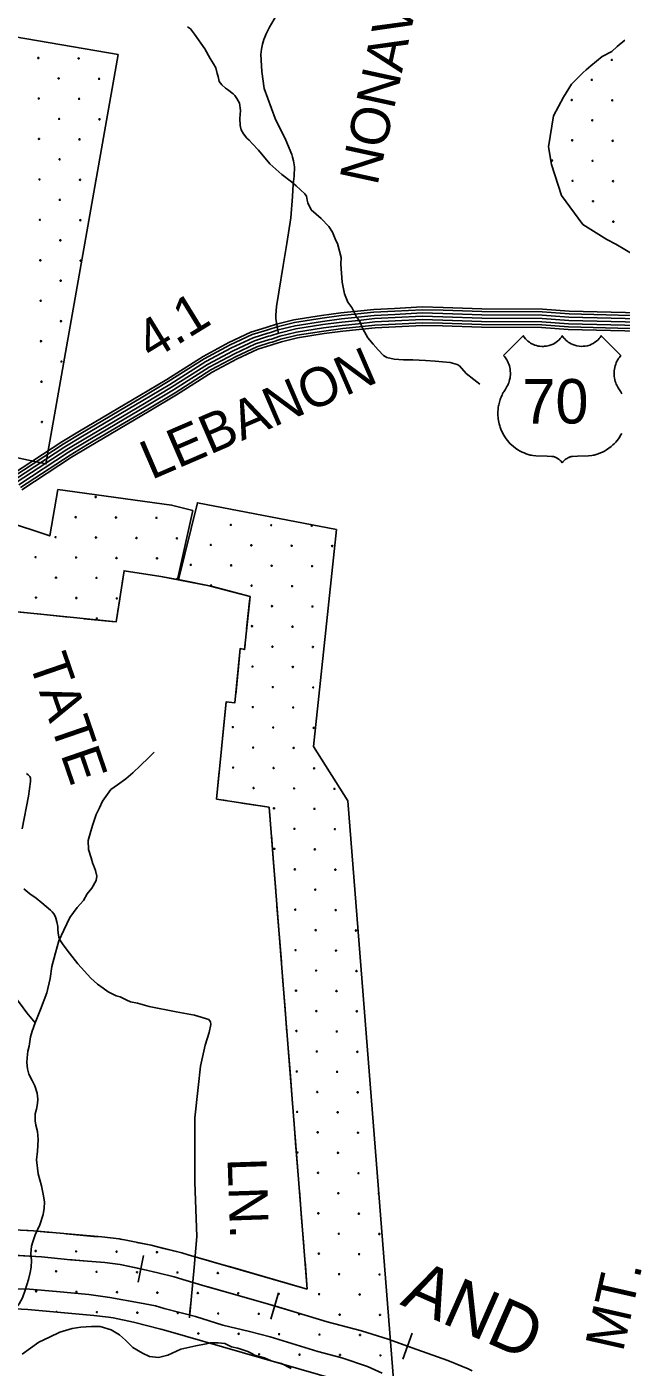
# Model space of a CAD drawing. Extents: x 1788175 to 1969470, y 584502 to 738744.
# Drawn here: x 1809595 to 1815246, y 681239 to 693983 of the extents above; entities that cross this region are included whole.
import ezdxf

# ---------------------------------------------------------------- set-up
doc = ezdxf.new("R2010")
doc.units = 0
for name, color, linetype in [('DESIGN - CONTOURS - Intermediate with optional Text', 7, 'Continuous'), ('DESIGN - EROSION CONTROL - Devices', 7, 'Continuous'), ('DESIGN - ROW - Right-of-Way and Easement Labels', 7, 'Continuous'), ('DESIGN - SCRATCH - User 1', 7, 'Continuous'), ('DESIGN - TRAFFIC CONTROL PERMANENT - Signalization', 7, 'Continuous'), ('DESIGN - TRANSPORTATION - Text', 7, 'Continuous'), ('DESIGN - VEGETATION - Features with Text', 7, 'Continuous'), ('SURVEY - CENTERLINE - Preliminary Text', 7, 'Continuous'), ('SURVEY - CONTOURS - Index with Text', 7, 'Continuous'), ('SURVEY - DRAINAGE - Bridge Deck with Text', 7, 'Continuous'), ('SURVEY - TRANSPORTATION - Roads', 7, 'Continuous'), ('SURVEY - UTILITIES - Cable (Underground) with Text', 7, 'Continuous'), ('SURVEY - VEGETATION - Features with Text', 7, 'Continuous')]:
    doc.layers.add(name, color=color, linetype=linetype)

msp = doc.modelspace()

# ---------------------------------------------------------------- linework, layer by layer
at = {"layer": 'DESIGN - CONTOURS - Intermediate with optional Text'}
for p, q in [((1810652, 682047), (1810705, 682301)), ((1811914, 681697), (1811988, 681947)), ((1813170, 681317), (1813258, 681562))]:
    msp.add_line(p, q, dxfattribs=at)
for points in [[(1808939, 682334), (1809735, 682289), (1810009, 682261), (1810173, 682247), (1810338, 682233), (1810482, 682215), (1810703, 682169), (1810841, 682135), (1810997, 682097), (1811109, 682063), (1811292, 682010), (1811550, 681937), (1811894, 681839), (1812169, 681757), (1812452, 681672), (1812778, 681584), (1813029, 681506), (1813304, 681407), (1813599, 681303), (1813791, 681223)], [(1809367, 682310), (1809735, 682289), (1810009, 682261), (1810025, 682259)], [(1810025, 682259), (1810173, 682247), (1810338, 682233), (1810482, 682215), (1810679, 682174)], [(1810679, 682174), (1810703, 682169), (1810841, 682135), (1810997, 682097), (1811109, 682063), (1811292, 682010), (1811316, 682004)], [(1811316, 682004), (1811550, 681937), (1811894, 681839), (1811951, 681822)], [(1811951, 681822), (1812169, 681757), (1812452, 681672), (1812584, 681636)], [(1812584, 681636), (1812778, 681584), (1813029, 681506), (1813214, 681440)], [(1813214, 681440), (1813304, 681407), (1813599, 681303), (1813791, 681223), (1813830, 681206)]]:
    msp.add_lwpolyline(points, dxfattribs=at)
at = {"layer": 'DESIGN - EROSION CONTROL - Devices'}
for centre in [(1809704, 693686), (1810088, 693682), (1815157, 693668), (1809898, 693492), (1810283, 693488), (1814967, 693478), (1809708, 693301), (1810092, 693298), (1814776, 693287), (1815161, 693284), (1809902, 693107), (1810286, 693103), (1814971, 693093), (1809711, 692917), (1810096, 692913), (1814780, 692903), (1815165, 692899), (1809906, 692723), (1814590, 692712), (1814974, 692709), (1809715, 692532), (1810100, 692528), (1814784, 692518), (1815168, 692515), (1809909, 692338), (1814978, 692324), (1809719, 692148), (1810103, 692144), (1815172, 692130), (1809913, 691953), (1809723, 691763), (1810107, 691759), (1809917, 691569), (1809726, 691378), (1809920, 691184), (1809730, 690994), (1809924, 690800), (1809734, 690609), (1809738, 690225), (1809741, 689840), (1810249, 689512), (1810059, 689321), (1810443, 689318), (1810828, 689314), (1811534, 689247), (1811919, 689244), (1812304, 689240), (1809868, 689131), (1810253, 689127), (1810637, 689123), (1811022, 689120), (1811344, 689057), (1811729, 689053), (1812113, 689049), (1812498, 689046), (1809678, 688940), (1810063, 688937), (1810447, 688933), (1810832, 688929), (1811154, 688867), (1811538, 688863), (1811923, 688859), (1812307, 688855), (1809872, 688746), (1810257, 688743), (1811348, 688672), (1811732, 688669), (1812117, 688665), (1809682, 688556), (1810066, 688552), (1810451, 688548), (1811926, 688475), (1812311, 688471), (1810260, 688358), (1811736, 688284), (1812121, 688280), (1811930, 688090), (1812315, 688086), (1811740, 687900), (1812124, 687896), (1811934, 687705), (1812318, 687702), (1811744, 687515), (1812128, 687511), (1811553, 687325), (1811938, 687321), (1812322, 687317), (1811747, 687130), (1812132, 687127), (1811557, 686940), (1811941, 686936), (1812326, 686933), (1811751, 686746), (1812136, 686742), (1812520, 686738), (1811945, 686552), (1812330, 686548), (1812139, 686358), (1812524, 686354), (1811949, 686167), (1812333, 686163), (1812143, 685973), (1812528, 685969), (1812337, 685779), (1812147, 685589), (1812531, 685585), (1812341, 685394), (1812725, 685391), (1812150, 685204), (1812535, 685200), (1812345, 685010), (1812729, 685006), (1812154, 684819), (1812539, 684816), (1812348, 684625), (1812733, 684622), (1812158, 684435), (1812542, 684431), (1812352, 684241), (1812737, 684237), (1812162, 684050), (1812546, 684047), (1812356, 683856), (1812740, 683852), (1812165, 683666), (1812550, 683662), (1812360, 683472), (1812744, 683468), (1812169, 683281), (1812554, 683277), (1812363, 683087), (1812748, 683083), (1812557, 682893), (1812367, 682702), (1812752, 682699), (1812561, 682508), (1812946, 682505), (1809679, 682344), (1810063, 682340), (1810448, 682337), (1810833, 682333), (1812371, 682318), (1812755, 682314), (1809873, 682150), (1810258, 682146), (1810642, 682142), (1811027, 682139), (1811411, 682135), (1812565, 682124), (1812949, 682120), (1809683, 681960), (1810067, 681956), (1810452, 681952), (1810836, 681948), (1811221, 681945), (1811605, 681941), (1811990, 681937), (1812374, 681933), (1812759, 681930), (1810261, 681762), (1810646, 681758), (1811030, 681754), (1811415, 681750), (1811800, 681747), (1812184, 681743), (1812569, 681739), (1812953, 681736), (1811225, 681560), (1811609, 681556), (1811994, 681553), (1812378, 681549), (1812763, 681545), (1811803, 681362), (1812188, 681358), (1812572, 681355), (1812957, 681351)]:
    msp.add_circle(centre, 5.28, dxfattribs=at)
for centre, start, end in [((1810290, 692719), 130.2848, 209.7236), ((1811026, 688735), 44.9488, 290.1383), ((1812942, 682889), 98.5783, 270.4574), ((1809877, 681765), 321.2621, 208.4208)]:
    msp.add_arc(centre, 5.28, start, end, dxfattribs=at)
at = {"layer": 'DESIGN - SCRATCH - User 1'}
for p, q in [((1811049, 688726), (1811349, 688664)), ((1811349, 688664), (1811718, 688566)), ((1811399, 686640), (1811899, 686562)), ((1813094, 680961), (1812647, 686623)), ((1811899, 686562), (1812261, 681980))]:
    msp.add_line(p, q, dxfattribs=at)
for points in [[(1809243, 694669), (1809149, 693943), (1810462, 693718)], [(1815280, 693856), (1815207, 693796), (1815158, 693747), (1815064, 693699), (1814959, 693613), (1814913, 693573), (1814884, 693547), (1814774, 693438), (1814699, 693314), (1814602, 693135), (1814555, 692841), (1814582, 692673)], [(1810462, 693718), (1809776, 689827), (1809250, 689939), (1809219, 689666), (1809187, 689328), (1808480, 689389)], [(1814582, 692673), (1814680, 692378), (1814882, 692102), (1815111, 691962), (1815196, 691917), (1815368, 691816), (1815509, 691755), (1815664, 691688), (1815749, 691647), (1815916, 691574), (1816044, 691537), (1816113, 691512), (1816236, 691479), (1816378, 691451), (1816561, 691442), (1816683, 691464)], [(1811027, 688727), (1811172, 689383), (1810971, 689436), (1809890, 689583), (1809812, 689142), (1809382, 689286), (1809360, 689294)], [(1812539, 689204), (1811216, 689457), (1811036, 688726), (1811049, 688726)], [(1812647, 686623), (1812321, 687139), (1812539, 689204)], [(1809112, 688470), (1809253, 688445), (1810444, 688325), (1810520, 688811), (1810870, 688756), (1811027, 688727)], [(1811718, 688566), (1811665, 688062), (1811623, 688072), (1811574, 687557), (1811490, 687564), (1811399, 686640)], [(1812261, 681980), (1811129, 682307), (1811069, 682326), (1810777, 682398), (1810554, 682445), (1810473, 682458), (1810307, 682477), (1809659, 682535), (1808968, 682572), (1808879, 682574)], [(1808321, 681810), (1808942, 681823), (1809605, 681787), (1810231, 681730), (1810371, 681715), (1810417, 681707), (1810609, 681667), (1810870, 681602), (1810917, 681588), (1813094, 680961)]]:
    msp.add_lwpolyline(points, dxfattribs=at)
at = {"layer": 'DESIGN - TRANSPORTATION - Text'}
for points in [[(1811124, 693984), (1811150, 693964), (1811188, 693914), (1811288, 693772), (1811337, 693682), (1811369, 693632), (1811393, 693592), (1811405, 693538), (1811413, 693510), (1811425, 693464), (1811449, 693430), (1811483, 693400), (1811503, 693386), (1811557, 693346), (1811573, 693330), (1811593, 693302), (1811617, 693258), (1811627, 693186), (1811620, 693110), (1811622, 693044), (1811632, 693002), (1811654, 692966), (1811688, 692924), (1811708, 692904), (1811738, 692874), (1811798, 692810), (1811904, 692680), (1812019, 692580), (1812111, 692510), (1812157, 692472), (1812237, 692396), (1812253, 692372), (1812261, 692336), (1812267, 692310), (1812297, 692244), (1812395, 692160), (1812466, 692084), (1812500, 692030), (1812532, 691952), (1812548, 691921)], [(1812548, 691921), (1812585, 691789), (1812581, 691725), (1812592, 691555), (1812616, 691445), (1812648, 691364), (1812684, 691314), (1812730, 691226), (1812762, 691180), (1812787, 691119), (1812804, 691084), (1812836, 691027), (1812889, 690967), (1812935, 690910), (1812985, 690857), (1813017, 690839), (1813088, 690822), (1813176, 690815), (1813265, 690815), (1813385, 690811), (1813478, 690804), (1813548, 690797), (1813619, 690790), (1813687, 690772), (1813708, 690758), (1813772, 690687), (1813846, 690630), (1813901, 690584)], [(1810807, 687087), (1810751, 687031), (1810675, 686959), (1810603, 686889), (1810535, 686833), (1810457, 686776), (1810395, 686730), (1810314, 686620), (1810286, 686558), (1810254, 686494), (1810218, 686390), (1810196, 686314), (1810178, 686248), (1810180, 686160), (1810206, 686082), (1810222, 686025), (1810228, 686013), (1810247, 685961), (1810259, 685909), (1810255, 685867), (1810213, 685793), (1810169, 685741), (1810133, 685675), (1810073, 685609), (1810003, 685513), (1809947, 685395), (1809899, 685294), (1809868, 685178), (1809834, 685050), (1809816, 684936), (1809786, 684798), (1809726, 684640), (1809674, 684514)], [(1808495, 686196), (1808563, 686142), (1808618, 686060), (1808618, 685952), (1808604, 685843), (1808604, 685762), (1808618, 685694), (1808631, 685585), (1808699, 685477), (1808767, 685409), (1808835, 685314), (1808916, 685192), (1808970, 685111), (1809011, 685084), (1809065, 685056), (1809147, 685016), (1809241, 684948), (1809323, 684894), (1809377, 684866), (1809431, 684826), (1809526, 684704), (1809594, 684609), (1809674, 684514)], [(1809674, 684514), (1809647, 684433), (1809630, 684380), (1809616, 684290), (1809603, 684244), (1809597, 684181), (1809596, 684137), (1809601, 684075), (1809614, 684024), (1809646, 683966), (1809670, 683914), (1809694, 683845), (1809700, 683787), (1809697, 683745), (1809686, 683692), (1809675, 683648), (1809674, 683581), (1809680, 683540), (1809696, 683481), (1809704, 683405), (1809695, 683292), (1809688, 683212), (1809703, 683077), (1809735, 682963), (1809754, 682868), (1809762, 682808), (1809761, 682752), (1809750, 682690)], [(1809750, 682690), (1809719, 682594), (1809675, 682496), (1809652, 682431), (1809638, 682389), (1809633, 682319), (1809640, 682253), (1809636, 682189), (1809627, 682140), (1809611, 682072), (1809580, 681970), (1809555, 681899), (1809522, 681840), (1809488, 681796), (1809455, 681755), (1809437, 681706), (1809422, 681645), (1809417, 681585), (1809398, 681518), (1809385, 681432), (1809366, 681379), (1809350, 681338), (1809333, 681296), (1809312, 681251)], [(1809552, 681364), (1809710, 681478), (1809810, 681525), (1809910, 681571), (1810025, 681607), (1810108, 681619), (1810210, 681625), (1810292, 681627), (1810398, 681593), (1810476, 681547), (1810532, 681497), (1810604, 681427), (1810694, 681372), (1810760, 681342), (1810846, 681332), (1810936, 681352), (1811060, 681412), (1811202, 681441), (1811300, 681460), (1811337, 681471), (1811413, 681471), (1811477, 681464), (1811541, 681434), (1811601, 681419), (1811695, 681389), (1811733, 681370)], [(1811733, 681370), (1811759, 681355), (1811855, 681327), (1811917, 681299), (1812017, 681273), (1812107, 681227)]]:
    msp.add_lwpolyline(points, dxfattribs=at)
at = {"layer": 'SURVEY - CENTERLINE - Preliminary Text'}
for points in [[(1815687, 691256), (1814752, 691279), (1814497, 691297), (1813922, 691301), (1813553, 691314), (1813353, 691319), (1813092, 691305), (1812893, 691296), (1812738, 691278), (1812580, 691262), (1812398, 691238), (1812135, 691196), (1811968, 691155), (1811888, 691129), (1811870, 691125), (1811726, 691080), (1811517, 690981), (1811270, 690849), (1810925, 690631), (1810669, 690477), (1810095, 690139), (1809927, 690038), (1809457, 689730)], [(1815687, 691230), (1814751, 691253), (1814496, 691272), (1813921, 691275), (1813552, 691288), (1813353, 691293), (1813093, 691280), (1812895, 691270), (1812741, 691253), (1812583, 691237), (1812402, 691213), (1812140, 691171), (1811975, 691131), (1811895, 691104), (1811877, 691100), (1811736, 691056), (1811528, 690958), (1811282, 690827), (1810939, 690609), (1810682, 690455), (1810108, 690117), (1809941, 690016), (1809470, 689708)], [(1815686, 691199), (1814749, 691222), (1814495, 691241), (1813921, 691244), (1813551, 691257), (1813354, 691262), (1813095, 691249), (1812898, 691239), (1812744, 691222), (1812587, 691206), (1812406, 691182), (1812146, 691141), (1811984, 691101), (1811903, 691074), (1811885, 691070), (1811747, 691027), (1811542, 690930), (1811298, 690800), (1810955, 690583), (1810698, 690429), (1810124, 690090), (1809957, 689990), (1809487, 689682)], [(1815685, 691168), (1814748, 691191), (1814494, 691210), (1813920, 691213), (1813550, 691226), (1813354, 691231), (1813096, 691218), (1812900, 691208), (1812747, 691191), (1812590, 691175), (1812410, 691152), (1812152, 691110), (1811992, 691071), (1811912, 691044), (1811893, 691040), (1811758, 690998), (1811556, 690902), (1811314, 690773), (1810971, 690557), (1810714, 690402), (1810140, 690063), (1809974, 689964), (1809503, 689656)], [(1815684, 691137), (1814746, 691160), (1814493, 691179), (1813919, 691182), (1813549, 691195), (1813355, 691200), (1813098, 691187), (1812903, 691177), (1812750, 691160), (1812594, 691144), (1812415, 691121), (1812159, 691080), (1812001, 691041), (1811920, 691014), (1811901, 691010), (1811770, 690969), (1811570, 690875), (1811329, 690746), (1810988, 690530), (1810730, 690375), (1810156, 690037), (1809990, 689938), (1809519, 689629)], [(1815684, 691106), (1814745, 691129), (1814491, 691148), (1813919, 691151), (1813548, 691164), (1813355, 691169), (1813099, 691156), (1812905, 691146), (1812754, 691129), (1812598, 691114), (1812419, 691090), (1812165, 691050), (1812009, 691012), (1811928, 690984), (1811909, 690980), (1811781, 690940), (1811584, 690847), (1811345, 690720), (1811004, 690504), (1810746, 690349), (1810171, 690010), (1810007, 689911), (1809535, 689603)], [(1815683, 691082), (1814743, 691104), (1814490, 691123), (1813918, 691127), (1813548, 691140), (1813356, 691144), (1813101, 691131), (1812907, 691122), (1812756, 691105), (1812600, 691089), (1812423, 691066), (1812170, 691025), (1812016, 690988), (1811935, 690961), (1811915, 690956), (1811790, 690917), (1811595, 690825), (1811357, 690698), (1811017, 690483), (1810758, 690327), (1810184, 689989), (1810020, 689890), (1809548, 689582)]]:
    msp.add_lwpolyline(points, dxfattribs=at)
at = {"layer": 'SURVEY - CONTOURS - Index with Text'}
for points in [[(1812014, 694169), (1811901, 693978), (1811875, 693923), (1811847, 693861), (1811835, 693819), (1811825, 693771), (1811820, 693718), (1811829, 693559), (1811852, 693397), (1811956, 693110), (1812057, 692904), (1812113, 692768), (1812121, 692744), (1812129, 692708), (1812139, 692650), (1812136, 692562), (1812128, 692488), (1812122, 692370), (1812104, 692166), (1812067, 691923), (1812032, 691714), (1811990, 691461), (1811970, 691322), (1811962, 691242), (1811962, 691207), (1811988, 691063)], [(1812974, 681183), (1812833, 681247), (1812591, 681329), (1812361, 681387), (1812113, 681466), (1811908, 681528), (1811712, 681580), (1811458, 681638), (1811198, 681722), (1810902, 681797), (1810817, 681821), (1810667, 681851), (1810385, 681901), (1810183, 681930), (1809877, 681958), (1809619, 681980), (1809379, 681987)]]:
    msp.add_lwpolyline(points, dxfattribs=at)
at = {"layer": 'SURVEY - DRAINAGE - Bridge Deck with Text'}
for points in [[(1814127, 690858), (1814315, 691045), (1814325, 691031), (1814337, 691016), (1814349, 691004), (1814360, 690994), (1814373, 690985), (1814385, 690976), (1814398, 690969), (1814412, 690962), (1814425, 690957), (1814442, 690952), (1814457, 690948), (1814474, 690946), (1814492, 690944), (1814500, 690944), (1814508, 690944), (1814516, 690945), (1814526, 690946), (1814536, 690947), (1814550, 690950), (1814562, 690953), (1814580, 690959), (1814598, 690967), (1814614, 690975), (1814628, 690985), (1814642, 690995), (1814655, 691007), (1814667, 691020), (1814678, 691033), (1814686, 691045), (1814693, 691035), (1814702, 691024), (1814710, 691015), (1814719, 691005), (1814731, 690995), (1814743, 690985), (1814756, 690977), (1814770, 690969), (1814786, 690961), (1814804, 690955), (1814826, 690949), (1814847, 690946), (1814865, 690944), (1814884, 690945), (1814905, 690947), (1814925, 690951), (1814947, 690957), (1814965, 690965), (1814980, 690972), (1814996, 690983), (1815011, 690993), (1815027, 691007), (1815037, 691019), (1815047, 691030), (1815057, 691045), (1815244, 690858)], [(1814127, 690858), (1814137, 690848), (1814145, 690837), (1814152, 690826), (1814159, 690816), (1814166, 690803), (1814172, 690789), (1814178, 690775), (1814183, 690760), (1814187, 690745), (1814190, 690729), (1814192, 690712), (1814193, 690690), (1814193, 690673), (1814191, 690658), (1814189, 690644), (1814185, 690625), (1814181, 690611), (1814177, 690598), (1814172, 690586), (1814167, 690576), (1814159, 690562), (1814152, 690550), (1814142, 690532), (1814129, 690511), (1814125, 690505), (1814119, 690494), (1814113, 690481), (1814109, 690472), (1814104, 690460), (1814100, 690450), (1814096, 690439), (1814092, 690427), (1814088, 690415), (1814085, 690401), (1814082, 690390), (1814080, 690378), (1814078, 690366), (1814076, 690353), (1814075, 690342), (1814074, 690330), (1814074, 690319), (1814074, 690308), (1814074, 690296), (1814074, 690284), (1814075, 690270), (1814077, 690254), (1814079, 690239), (1814082, 690224), (1814085, 690208), (1814091, 690189), (1814095, 690175), (1814102, 690157), (1814108, 690143), (1814113, 690132), (1814120, 690117), (1814130, 690100), (1814139, 690085), (1814151, 690067), (1814164, 690051), (1814177, 690035), (1814192, 690019), (1814204, 690007), (1814221, 689993), (1814241, 689977), (1814265, 689961), (1814285, 689949), (1814305, 689939), (1814323, 689931), (1814344, 689923), (1814363, 689917), (1814382, 689911), (1814392, 689909), (1814405, 689908), (1814435, 689905), (1814541, 689902), (1814588, 689899), (1814593, 689899), (1814598, 689897), (1814603, 689896), (1814608, 689895), (1814613, 689893), (1814617, 689891), (1814622, 689889), (1814627, 689887), (1814632, 689885), (1814636, 689883), (1814640, 689880), (1814648, 689875), (1814658, 689868), (1814666, 689861), (1814674, 689853), (1814680, 689846), (1814686, 689838)], [(1815244, 690858), (1815235, 690848), (1815227, 690837), (1815219, 690826), (1815213, 690816), (1815206, 690803), (1815199, 690789), (1815194, 690775), (1815189, 690760), (1815185, 690745), (1815182, 690729), (1815179, 690712), (1815178, 690690), (1815179, 690673), (1815180, 690658), (1815182, 690644), (1815186, 690625), (1815190, 690611), (1815194, 690598), (1815199, 690586), (1815204, 690576), (1815212, 690562), (1815219, 690550), (1815230, 690532), (1815243, 690511), (1815246, 690505), (1815252, 690494)], [(1815251, 690117), (1815241, 690100), (1815232, 690085), (1815220, 690067), (1815208, 690051), (1815194, 690035), (1815180, 690019), (1815167, 690007), (1815150, 689993), (1815130, 689977), (1815106, 689961), (1815086, 689949), (1815067, 689939), (1815048, 689931), (1815028, 689923), (1815008, 689917), (1814989, 689911), (1814979, 689909), (1814967, 689908), (1814936, 689905), (1814831, 689902), (1814783, 689899), (1814779, 689899), (1814774, 689897), (1814769, 689896), (1814764, 689895), (1814759, 689893), (1814754, 689891), (1814749, 689889), (1814745, 689887), (1814739, 689885), (1814736, 689883), (1814732, 689880), (1814723, 689875), (1814714, 689868), (1814705, 689861), (1814698, 689853), (1814691, 689846), (1814686, 689838)]]:
    msp.add_lwpolyline(points, dxfattribs=at)
at = {"layer": 'SURVEY - TRANSPORTATION - Roads'}
for points in [[(1809552, 686356), (1809610, 686668), (1809630, 686806), (1809631, 686822), (1809630, 686830), (1809629, 686840), (1809625, 686850), (1809622, 686856), (1809613, 686866), (1809609, 686870), (1809593, 686884)], [(1810647, 684699), (1810581, 684713), (1810545, 684729), (1810483, 684759), (1810443, 684771), (1810367, 684809), (1810321, 684843), (1810267, 684881), (1810203, 684937), (1810081, 685073), (1810002, 685177), (1809940, 685255), (1809910, 685301), (1809900, 685327), (1809893, 685370), (1809891, 685398), (1809888, 685429), (1809881, 685473), (1809871, 685508), (1809864, 685526), (1809850, 685548), (1809837, 685569), (1809819, 685585), (1809739, 685653), (1809683, 685699), (1809623, 685741), (1809567, 685787)], [(1811143, 681710), (1811186, 682188), (1811210, 682482), (1811193, 682998), (1811192, 683611), (1811223, 683899), (1811245, 684102), (1811292, 684302), (1811330, 684422), (1811344, 684496), (1811340, 684524), (1811324, 684544), (1811302, 684552), (1811254, 684568), (1811188, 684586), (1811014, 684618), (1810759, 684668), (1810647, 684699)]]:
    msp.add_lwpolyline(points, dxfattribs=at)
at = {"layer": 'SURVEY - UTILITIES - Cable (Underground) with Text'}
msp.add_lwpolyline([(1811153, 681852), (1811141, 681737)], dxfattribs=at)
at = {"layer": 'SURVEY - VEGETATION - Features with Text'}
for points in [[(1811329, 688669), (1810870, 688756), (1810520, 688811), (1810444, 688325), (1809253, 688445), (1809165, 688463), (1808803, 688489)], [(1810662, 688789), (1810520, 688811), (1810501, 688692)], [(1810923, 688746), (1810870, 688756), (1810662, 688789)], [(1811329, 688669), (1811070, 688718)], [(1811718, 688566), (1811329, 688669)], [(1810478, 688544), (1810444, 688325), (1810402, 688329)], [(1811399, 686640), (1811490, 687564), (1811574, 687557), (1811623, 688072), (1811665, 688062), (1811718, 688566)], [(1811718, 688566), (1811463, 688634)], [(1811713, 688521), (1811718, 688566)], [(1809727, 688397), (1809465, 688424)], [(1811685, 688258), (1811713, 688521)], [(1809990, 688370), (1809727, 688397)], [(1810402, 688329), (1810139, 688355)], [(1811606, 687899), (1811623, 688072), (1811665, 688062), (1811670, 688109)], [(1811582, 687636), (1811606, 687899)], [(1811466, 687315), (1811490, 687564), (1811504, 687563)], [(1811440, 687052), (1811466, 687315)], [(1811399, 686640), (1811425, 686903)], [(1811899, 686562), (1811399, 686640)], [(1811490, 686626), (1811399, 686640)], [(1811899, 686562), (1811638, 686603)], [(1812261, 681980), (1811899, 686564)], [(1811908, 686448), (1811899, 686564)], [(1811941, 686035), (1811920, 686298)], [(1811961, 685772), (1811941, 686035)], [(1811994, 685359), (1811973, 685622)], [(1812015, 685096), (1811994, 685359)], [(1812048, 684683), (1812027, 684947)], [(1812068, 684420), (1812048, 684683)], [(1812101, 684008), (1812080, 684271)], [(1812122, 683744), (1812101, 684008)], [(1812154, 683332), (1812134, 683595)], [(1812175, 683068), (1812154, 683332)], [(1812208, 682656), (1812187, 682919)], [(1808879, 682574), (1808968, 682572), (1809659, 682535), (1810307, 682477), (1810473, 682458), (1810554, 682445), (1810777, 682398), (1811069, 682326), (1811129, 682307), (1811425, 682222)], [(1812229, 682393), (1812208, 682656)], [(1809556, 682541), (1809659, 682535), (1809820, 682521)], [(1809969, 682507), (1810232, 682483)], [(1810232, 682483), (1810307, 682477), (1810473, 682458), (1810494, 682454)], [(1810642, 682426), (1810777, 682398), (1810899, 682368)], [(1810899, 682368), (1811069, 682326), (1811129, 682307), (1811154, 682300)], [(1811298, 682259), (1811425, 682222)], [(1811425, 682222), (1811552, 682187), (1812261, 681980)], [(1811425, 682222), (1811552, 682187), (1811679, 682150)], [(1812261, 681980), (1812240, 682243)], [(1811823, 682108), (1812077, 682034)], [(1812077, 682034), (1812261, 681980)]]:
    msp.add_lwpolyline(points, dxfattribs=at)

# ---------------------------------------------------------------- texts
at = {"layer": 'DESIGN - ROW - Right-of-Way and Easement Labels'}
for s, rotation, p in [('NONAVILLE', 77.7489, (1812927, 692464)), ('LEBANON', 23.3532, (1810779, 689673)), ('TATE', 288.9409, (1809610, 687950)), ('LN.', 271.8932, (1811503, 683225)), ('MT. ', 77.285, (1815262, 681376))]:
    msp.add_text(s, height=370, rotation=rotation, dxfattribs=at).set_placement(p)
at = {"layer": 'DESIGN - TRAFFIC CONTROL PERMANENT - Signalization'}
msp.add_text('4.1', height=369.6, rotation=31.6093, dxfattribs=at).set_placement((1810782, 690804))
at = {"layer": 'DESIGN - VEGETATION - Features with Text'}
msp.add_text('AND', height=475, rotation=336.2208, dxfattribs=at).set_placement((1813136, 681838))
at = {"layer": 'SURVEY - DRAINAGE - Bridge Deck with Text'}
msp.add_text('70', height=422.4, dxfattribs=at).set_placement((1814307, 690211))

doc.saveas('drawing.dxf')
